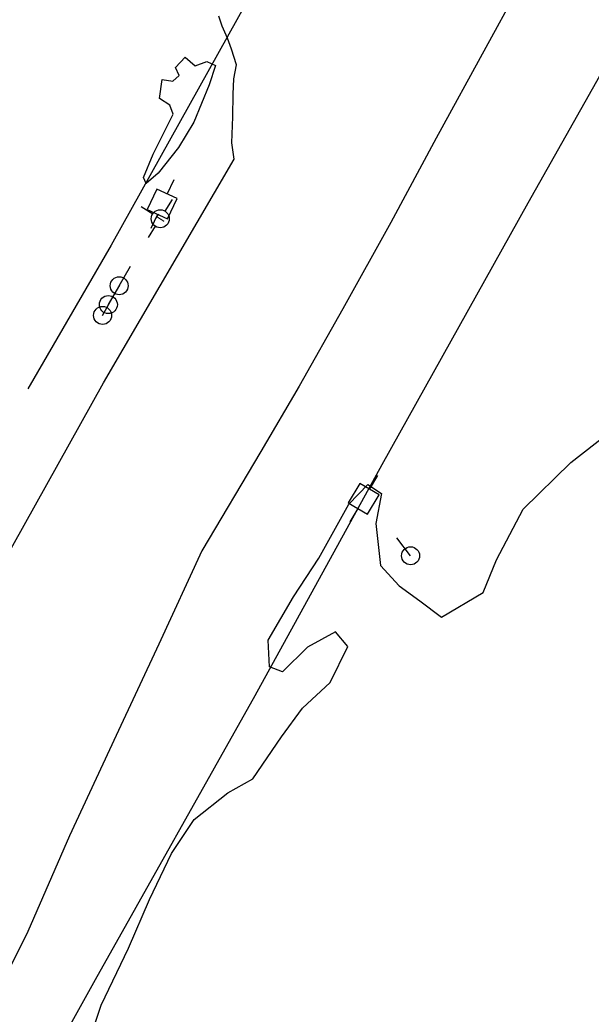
# Model space of a CAD drawing. Extents: x 2161152 to 2175754, y 602179 to 617749.
# Drawn here: x 2173198.7 to 2173325.7, y 615244 to 615465 of the extents above; entities that cross this region are included whole.
import ezdxf

# ---------------------------------------------------------------- set-up
doc = ezdxf.new("R2010")
doc.units = 0
for name, color, linetype in [('RD_EX_Driveway_Asphalt', 7, 'Continuous'), ('RD_EX_Fence_ChLk', 7, 'Continuous'), ('RD_EX_Road', 7, 'Continuous'), ('RD_EX_UT', 7, 'Continuous'), ('RD_EX_VEG', 7, 'Continuous')]:
    doc.layers.add(name, color=color, linetype=linetype)

msp = doc.modelspace()

# ---------------------------------------------------------------- linework, layer by layer
at = {"layer": 'RD_EX_Driveway_Asphalt'}
msp.add_lwpolyline([(2173246.35, 615434), (2173245.87, 615437.68), (2173246.07, 615443.45), (2173246.13, 615448.44), (2173246.3, 615451.85), (2173246.87, 615455), (2173245.79, 615458.49), (2173244.84, 615460.93), (2173243.69, 615463.57), (2173242.93, 615465.81)], dxfattribs=at)
at = {"layer": 'RD_EX_Fence_ChLk'}
for points in [[(2173357.97, 615662.09), (2173326.16, 615607.33), (2173277.04, 615518.94), (2173251.64, 615473.42), (2173219, 615414.87), (2173200.53, 615382.97)], [(2173355.63, 615502.38), (2173341.84, 615477.91), (2173311.58, 615424.23), (2173279.17, 615366.05), (2173250.91, 615314.76), (2173215.5, 615251.65), (2173188.18, 615202.66), (2173161.58, 615155.19), (2173087.55, 615023.77), (2173205.02, 614957.05), (2173296.02, 615068.65), (2173468.11, 615299.84), (2173503.11, 615360.81), (2173534.6, 615415.1), (2173553.32, 615447.99), (2173576.24, 615487.44)]]:
    msp.add_lwpolyline(points, dxfattribs=at)
at = {"layer": 'RD_EX_Road'}
for points in [[(2173322.5, 615495.78), (2173302.26, 615458.84), (2173291.21, 615438.7), (2173281.15, 615419.94), (2173270.5, 615400.72), (2173260.78, 615383.59), (2173252.26, 615369.08), (2173239.16, 615346.93), (2173229.61, 615326.19), (2173220.13, 615305.92), (2173209.78, 615283.61), (2173200.49, 615262.34), (2173189.89, 615241.22)], [(2173134.24, 615232.91), (2173142.36, 615247.69), (2173165, 615289), (2173192.04, 615339.08), (2173217.34, 615384.32), (2173246.35, 615434)]]:
    msp.add_lwpolyline(points, dxfattribs=at)
at = {"layer": 'RD_EX_UT'}
for p, q in [((2173231.44, 615426.23), (2173232.99, 615429.52)), ((2173229.15, 615427.38), (2173227.03, 615422.85)), ((2173233.68, 615425.26), (2173229.15, 615427.38)), ((2173225.66, 615423.5), (2173228.25, 615421.86)), ((2173230.99, 615422.48), (2173232.64, 615425.07)), ((2173231.56, 615420.73), (2173233.68, 615425.26)), ((2173227.03, 615422.85), (2173231.56, 615420.73)), ((2173227.89, 615418.66), (2173229.37, 615421.8)), ((2173227.28, 615416.63), (2173228.85, 615419.1)), ((2173220.8, 615405.88), (2173223.29, 615410.21)), ((2173218.39, 615401.7), (2173220.98, 615405.98)), ((2173217.11, 615399.29), (2173219.55, 615403.66)), ((2173274.26, 615361.95), (2173271.7, 615357.66)), ((2173278.55, 615359.39), (2173274.26, 615361.95)), ((2173276.42, 615360.58), (2173278.29, 615363.7)), ((2173271.7, 615357.66), (2173275.99, 615355.1)), ((2173275.99, 615355.1), (2173278.55, 615359.39)), ((2173272.14, 615353.4), (2173273.92, 615356.38)), ((2173285.56, 615345.86), (2173282.51, 615349.83))]:
    msp.add_line(p, q, dxfattribs=at)
for centre in [(2173229.93, 615420.78), (2173220.8, 615405.88), (2173218.39, 615401.7), (2173217.11, 615399.29), (2173285.56, 615345.86)]:
    msp.add_circle(centre, 2, dxfattribs=at)
at = {"layer": 'RD_EX_VEG'}
for points in [[(2173233.95, 615436.58), (2173229.49, 615430.93), (2173226.83, 615428.6), (2173226.19, 615429.92), (2173228.36, 615435.14), (2173230.64, 615439.71), (2173232.8, 615444.02), (2173232.03, 615446), (2173229.75, 615447.54), (2173230.33, 615451.73), (2173232.75, 615451.37), (2173234.15, 615452.6), (2173233.32, 615454.39), (2173235.45, 615456.72), (2173237.72, 615454.79), (2173240.29, 615455.75), (2173242.18, 615454.87), (2173240.82, 615450.55), (2173237.37, 615442.26), (2173233.95, 615436.58)], [(2173213.79, 615236.82), (2173216.79, 615245.98), (2173222.85, 615258.64), (2173227.57, 615269.48), (2173232.42, 615279.67), (2173237.5, 615287.22), (2173244.93, 615293.17), (2173250.48, 615296.26), (2173256.9, 615305.64), (2173261.57, 615312.02), (2173267.68, 615317.72), (2173271.59, 615325.69), (2173268.87, 615329), (2173262.66, 615325.53), (2173257.07, 615320.08), (2173254.2, 615321.17), (2173253.88, 615327.08), (2173259.51, 615336.73), (2173265.13, 615345.33), (2173271.84, 615357.33), (2173276.09, 615361.74), (2173279.09, 615359.74), (2173277.82, 615353.06), (2173278.89, 615343.72), (2173283.04, 615339.21), (2173287.6, 615335.87), (2173292.41, 615332.26), (2173301.67, 615337.67), (2173304.65, 615344.99), (2173310.56, 615356.21), (2173321.19, 615366.58), (2173334.98, 615377.45)]]:
    msp.add_lwpolyline(points, dxfattribs=at)

# ---------------------------------------------------------------- texts
at = {"layer": 'RD_EX_UT'}
msp.add_text('T', height=2, rotation=57.5515, dxfattribs=at).set_placement((2173230.36, 615419.5))

doc.saveas('drawing.dxf')
